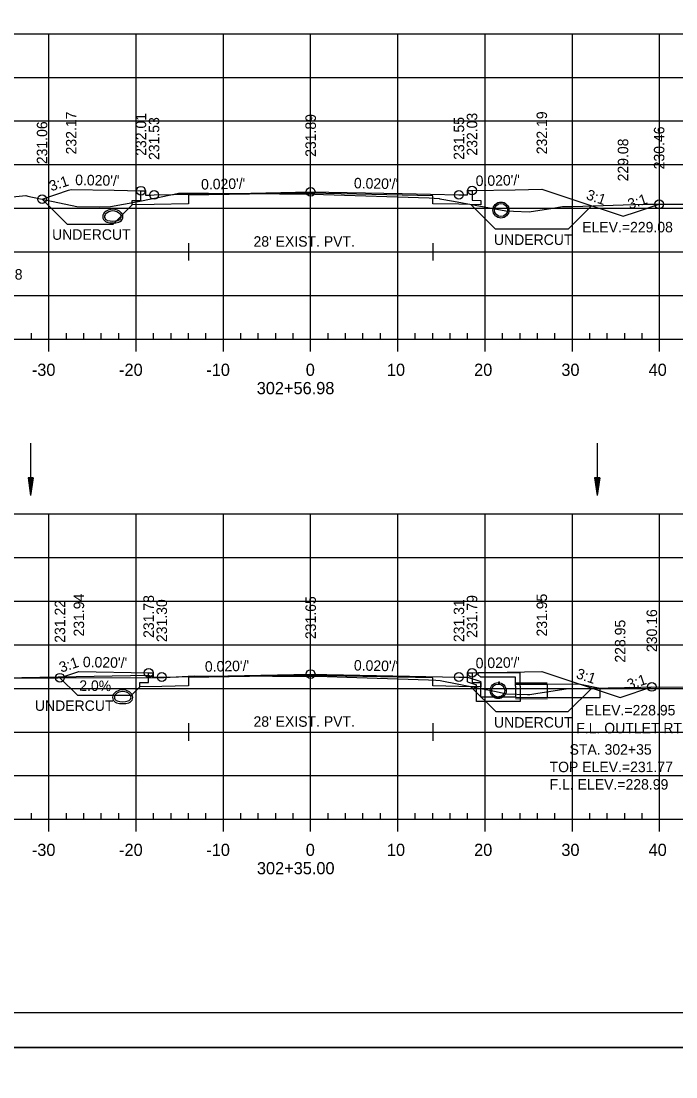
# Model space of a CAD drawing. Extents: x 1386544 to 1388153, y 379785 to 390999.
# Drawn here: x 1386681.7 to 1386756.7, y 384488.6 to 384609.5 of the extents above; entities that cross this region are included whole.
import ezdxf

# ---------------------------------------------------------------- set-up
doc = ezdxf.new("R2010")
doc.units = 0
for name, color, linetype in [('R_Alt Surface', 7, 'Continuous'), ('R_Axis', 7, 'Continuous'), ('R_Axis Annot', 7, 'Continuous'), ('R_Border', 7, 'Continuous'), ('R_Dimension', 7, 'Continuous'), ('R_Drive', 7, 'Continuous'), ('R_Exist Surface', 7, 'Continuous'), ('R_Fin Surface', 7, 'Continuous'), ('R_Fin Surface Annot', 7, 'Continuous'), ('R_Grid', 7, 'Continuous'), ('R_No Plot', 7, 'Continuous'), ('R_Water', 7, 'Continuous'), ('R_Water Annot', 7, 'Continuous')]:
    doc.layers.add(name, color=color, linetype=linetype)

msp = doc.modelspace()

# ---------------------------------------------------------------- linework, layer by layer
at = {"layer": 'R_Alt Surface'}
for points in [[(1386733.37, 384590.12), (1386733.37, 384589.02), (1386734.37, 384589), (1386734.37, 384588.5), (1386731.87, 384588.55), (1386728.87, 384588.61), (1386728.87, 384589.53), (1386714.87, 384589.81), (1386700.87, 384589.6), (1386700.87, 384588.61), (1386696.92, 384588.53), (1386694.42, 384588.48), (1386694.42, 384588.98), (1386695.42, 384589), (1386695.42, 384590.1)], [(1386700.87, 384584.09), (1386700.87, 384582.09)], [(1386728.87, 384584.09), (1386728.87, 384582.09)], [(1386700.87, 384583.09), (1386728.87, 384583.09)], [(1386733.37, 384534.87), (1386733.37, 384533.78), (1386734.37, 384533.76), (1386734.37, 384533.26), (1386731.87, 384533.31), (1386728.87, 384533.37), (1386728.87, 384534.28), (1386714.87, 384534.56), (1386700.87, 384534.35), (1386700.87, 384533.37), (1386697.8, 384533.31), (1386695.3, 384533.26), (1386695.3, 384533.76), (1386696.3, 384533.78), (1386696.3, 384534.87)], [(1386700.87, 384529.09), (1386700.87, 384527.09)], [(1386728.87, 384529.09), (1386728.87, 384527.09)], [(1386700.87, 384528.09), (1386728.87, 384528.09)]]:
    msp.add_lwpolyline(points, dxfattribs=at)
at = {"layer": 'R_Axis'}
for p, q in [((1386682.87, 384573.09), (1386682.87, 384573.79)), ((1386686.87, 384573.09), (1386686.87, 384573.79)), ((1386688.87, 384573.09), (1386688.87, 384573.79)), ((1386690.87, 384573.09), (1386690.87, 384573.79)), ((1386692.87, 384573.09), (1386692.87, 384573.79)), ((1386696.87, 384573.09), (1386696.87, 384573.79)), ((1386698.87, 384573.09), (1386698.87, 384573.79)), ((1386700.87, 384573.09), (1386700.87, 384573.79)), ((1386702.87, 384573.09), (1386702.87, 384573.79)), ((1386706.87, 384573.09), (1386706.87, 384573.79)), ((1386708.87, 384573.09), (1386708.87, 384573.79)), ((1386710.87, 384573.09), (1386710.87, 384573.79)), ((1386712.87, 384573.09), (1386712.87, 384573.79)), ((1386716.87, 384573.09), (1386716.87, 384573.79)), ((1386718.87, 384573.09), (1386718.87, 384573.79)), ((1386720.87, 384573.09), (1386720.87, 384573.79)), ((1386722.87, 384573.09), (1386722.87, 384573.79)), ((1386726.87, 384573.09), (1386726.87, 384573.79)), ((1386728.87, 384573.09), (1386728.87, 384573.79)), ((1386730.87, 384573.09), (1386730.87, 384573.79)), ((1386732.87, 384573.09), (1386732.87, 384573.79)), ((1386736.87, 384573.09), (1386736.87, 384573.79)), ((1386738.87, 384573.09), (1386738.87, 384573.79)), ((1386740.87, 384573.09), (1386740.87, 384573.79)), ((1386742.87, 384573.09), (1386742.87, 384573.79)), ((1386746.87, 384573.09), (1386746.87, 384573.79)), ((1386748.87, 384573.09), (1386748.87, 384573.79)), ((1386750.87, 384573.09), (1386750.87, 384573.79)), ((1386752.87, 384573.09), (1386752.87, 384573.79)), ((1386569.87, 384573.09), (1386859.87, 384573.09)), ((1386684.87, 384571.69), (1386684.87, 384573.09)), ((1386694.87, 384571.69), (1386694.87, 384573.09)), ((1386704.87, 384571.69), (1386704.87, 384573.09)), ((1386714.87, 384571.69), (1386714.87, 384573.09)), ((1386724.87, 384571.69), (1386724.87, 384573.09)), ((1386734.87, 384571.69), (1386734.87, 384573.09)), ((1386744.87, 384571.69), (1386744.87, 384573.09)), ((1386754.87, 384571.69), (1386754.87, 384573.09)), ((1386569.87, 384518.09), (1386859.87, 384518.09)), ((1386682.87, 384518.09), (1386682.87, 384518.79)), ((1386684.87, 384516.69), (1386684.87, 384518.09)), ((1386686.87, 384518.09), (1386686.87, 384518.79)), ((1386688.87, 384518.09), (1386688.87, 384518.79)), ((1386690.87, 384518.09), (1386690.87, 384518.79)), ((1386692.87, 384518.09), (1386692.87, 384518.79)), ((1386694.87, 384516.69), (1386694.87, 384518.09)), ((1386696.87, 384518.09), (1386696.87, 384518.79)), ((1386698.87, 384518.09), (1386698.87, 384518.79)), ((1386700.87, 384518.09), (1386700.87, 384518.79)), ((1386702.87, 384518.09), (1386702.87, 384518.79)), ((1386704.87, 384516.69), (1386704.87, 384518.09)), ((1386706.87, 384518.09), (1386706.87, 384518.79)), ((1386708.87, 384518.09), (1386708.87, 384518.79)), ((1386710.87, 384518.09), (1386710.87, 384518.79)), ((1386712.87, 384518.09), (1386712.87, 384518.79)), ((1386714.87, 384516.69), (1386714.87, 384518.09)), ((1386716.87, 384518.09), (1386716.87, 384518.79)), ((1386718.87, 384518.09), (1386718.87, 384518.79)), ((1386720.87, 384518.09), (1386720.87, 384518.79)), ((1386722.87, 384518.09), (1386722.87, 384518.79)), ((1386724.87, 384516.69), (1386724.87, 384518.09)), ((1386726.87, 384518.09), (1386726.87, 384518.79)), ((1386728.87, 384518.09), (1386728.87, 384518.79)), ((1386730.87, 384518.09), (1386730.87, 384518.79)), ((1386732.87, 384518.09), (1386732.87, 384518.79)), ((1386734.87, 384516.69), (1386734.87, 384518.09)), ((1386736.87, 384518.09), (1386736.87, 384518.79)), ((1386738.87, 384518.09), (1386738.87, 384518.79)), ((1386740.87, 384518.09), (1386740.87, 384518.79)), ((1386742.87, 384518.09), (1386742.87, 384518.79)), ((1386744.87, 384516.69), (1386744.87, 384518.09)), ((1386746.87, 384518.09), (1386746.87, 384518.79)), ((1386748.87, 384518.09), (1386748.87, 384518.79)), ((1386750.87, 384518.09), (1386750.87, 384518.79)), ((1386752.87, 384518.09), (1386752.87, 384518.79)), ((1386754.87, 384516.69), (1386754.87, 384518.09))]:
    msp.add_line(p, q, dxfattribs=at)
at = {"layer": 'R_Border'}
msp.add_line((1386873.05, 384495.92), (1386556.87, 384495.92), dxfattribs=at)
at = {"layer": 'R_Dimension'}
for p, q in [((1386684.08, 384589.14), (1386686.94, 384586.28)), ((1386694.42, 384588.48), (1386692.22, 384586.28)), ((1386733.23, 384588.53), (1386736.06, 384585.69)), ((1386747.08, 384588.37), (1386744.4, 384585.69)), ((1386686.13, 384534.31), (1386688.13, 384532.31)), ((1386695.3, 384533.26), (1386694.35, 384532.31)), ((1386733.25, 384533.28), (1386736.15, 384530.39)), ((1386747.09, 384533.13), (1386744.34, 384530.39))]:
    msp.add_line(p, q, dxfattribs=at)
for points in [[(1386686.94, 384586.28), (1386692.22, 384586.28)], [(1386744.4, 384585.69), (1386736.06, 384585.69)], [(1386688.13, 384532.31), (1386694.35, 384532.31)], [(1386744.34, 384530.39), (1386736.15, 384530.39)]]:
    msp.add_lwpolyline(points, dxfattribs=at)
at = {"layer": 'R_Drive'}
for p, q in [((1386696.3, 384534.57), (1386681.77, 384534.28)), ((1386696.8, 384534.37), (1386696.3, 384534.57))]:
    msp.add_line(p, q, dxfattribs=at)
at = {"layer": 'R_Exist Surface'}
for points in [[(1386677.97, 384589.12), (1386682.21, 384589.54), (1386682.45, 384589.49), (1386688.07, 384588.28), (1386690.72, 384588.27), (1386691.91, 384588.31), (1386694.9, 384588.81), (1386699.21, 384589.72), (1386699.72, 384589.82), (1386701.38, 384589.83), (1386701.39, 384589.83), (1386703.17, 384589.81), (1386715.34, 384589.69), (1386716.35, 384589.66), (1386728.44, 384589.3), (1386729.59, 384589.2), (1386729.69, 384589.19), (1386731.26, 384588.89), (1386737.26, 384587.78), (1386738.11, 384587.75), (1386739.93, 384587.69), (1386742.63, 384588.11), (1386743.76, 384588.29), (1386744.94, 384588.31), (1386753.01, 384588.55), (1386764.32, 384588.55)], [(1386680.87, 384534.28), (1386682.6, 384534.28), (1386685.88, 384534.31), (1386698.08, 384534.33), (1386701.52, 384534.54), (1386710.48, 384534.48), (1386715.61, 384534.47), (1386720.16, 384534.32), (1386728.38, 384534.07), (1386729.22, 384534.01), (1386729.72, 384533.98), (1386736.13, 384532.72), (1386737.31, 384532.47), (1386739.73, 384532.39), (1386739.99, 384532.39), (1386740.7, 384532.49), (1386744.4, 384533.09), (1386747.09, 384533.13), (1386752.72, 384533.24), (1386769.44, 384533.32)]]:
    msp.add_lwpolyline(points, dxfattribs=at)
at = {"layer": 'R_Fin Surface'}
for points in [[(1386684.08, 384589.14), (1386687.11, 384590.16), (1386687.42, 384590.26), (1386692.35, 384590.16), (1386695.42, 384590.1), (1386695.73, 384590.1), (1386695.92, 384590.1), (1386695.92, 384589.79), (1386695.92, 384589.6), (1386696.54, 384589.61), (1386696.92, 384589.62), (1386708.02, 384589.84), (1386714.87, 384589.98), (1386725.36, 384589.77), (1386731.87, 384589.64), (1386732.25, 384589.63), (1386732.87, 384589.62), (1386732.87, 384589.93), (1386732.87, 384590.12), (1386733.06, 384590.12), (1386733.37, 384590.12), (1386738.3, 384590.22), (1386741.37, 384590.28), (1386744.93, 384589.09), (1386750.68, 384587.17), (1386752.24, 384587.69), (1386754.82, 384588.55)], [(1386686.13, 384534.31), (1386688.3, 384535.03), (1386696.3, 384534.87), (1386696.8, 384534.87), (1386696.8, 384534.37), (1386697.8, 384534.39), (1386714.87, 384534.73), (1386731.87, 384534.39), (1386732.87, 384534.37), (1386732.87, 384534.87), (1386733.37, 384534.87), (1386741.37, 384535.03), (1386750.35, 384532.04), (1386753.98, 384533.25)]]:
    msp.add_lwpolyline(points, dxfattribs=at)
at = {"layer": 'R_Grid'}
for p, q in [((1386569.87, 384608.09), (1386859.87, 384608.09)), ((1386684.87, 384573.09), (1386684.87, 384608.09)), ((1386694.87, 384573.09), (1386694.87, 384608.09)), ((1386704.87, 384573.09), (1386704.87, 384608.09)), ((1386714.87, 384573.09), (1386714.87, 384608.09)), ((1386724.87, 384573.09), (1386724.87, 384608.09)), ((1386734.87, 384573.09), (1386734.87, 384608.09)), ((1386744.87, 384573.09), (1386744.87, 384608.09)), ((1386754.87, 384573.09), (1386754.87, 384608.09)), ((1386569.87, 384603.09), (1386859.87, 384603.09)), ((1386569.87, 384598.09), (1386859.87, 384598.09)), ((1386569.87, 384593.09), (1386859.87, 384593.09)), ((1386569.87, 384588.09), (1386859.87, 384588.09)), ((1386569.87, 384583.09), (1386859.87, 384583.09)), ((1386569.87, 384578.09), (1386859.87, 384578.09)), ((1386569.87, 384573.09), (1386859.87, 384573.09)), ((1386569.87, 384553.09), (1386859.87, 384553.09)), ((1386684.87, 384518.09), (1386684.87, 384553.09)), ((1386694.87, 384518.09), (1386694.87, 384553.09)), ((1386704.87, 384518.09), (1386704.87, 384553.09)), ((1386714.87, 384518.09), (1386714.87, 384553.09)), ((1386724.87, 384518.09), (1386724.87, 384553.09)), ((1386734.87, 384518.09), (1386734.87, 384553.09)), ((1386744.87, 384518.09), (1386744.87, 384553.09)), ((1386754.87, 384518.09), (1386754.87, 384553.09)), ((1386569.87, 384548.09), (1386859.87, 384548.09)), ((1386569.87, 384543.09), (1386859.87, 384543.09)), ((1386569.87, 384538.09), (1386859.87, 384538.09)), ((1386569.87, 384533.09), (1386859.87, 384533.09)), ((1386569.87, 384528.09), (1386859.87, 384528.09)), ((1386569.87, 384523.09), (1386859.87, 384523.09)), ((1386569.87, 384518.09), (1386859.87, 384518.09))]:
    msp.add_line(p, q, dxfattribs=at)
at = {"layer": 'R_No Plot'}
for p, q in [((1386736.51, 384533.83), (1386736.4, 384533.75)), ((1386738.37, 384533.74), (1386741.98, 384533.73)), ((1386736.51, 384532), (1386736.4, 384531.91)), ((1386738.37, 384531.91), (1386741.98, 384531.9)), ((1386544.47, 384491.94), (1386877.8, 384491.94)), ((1386544.47, 384491.94), (1386877.8, 384491.94))]:
    msp.add_line(p, q, dxfattribs=at)
for points in [[(1386544.46, 384705.28), (1386877.8, 384705.28), (1386877.8, 384491.94), (1386544.46, 384491.94)], [(1386790.79, 384701.38), (1386810.41, 384701.38), (1386810.41, 384691.5), (1386826.52, 384691.5), (1386849.72, 384691.5), (1386849.72, 384667.17), (1386873.05, 384667.17), (1386873.05, 384495.92), (1386556.87, 384495.92), (1386556.87, 384701.38)], [(1386544.46, 384491.94), (1386877.8, 384491.94), (1386877.8, 384278.6), (1386544.46, 384278.6)]]:
    msp.add_lwpolyline(points, close=True, dxfattribs=at)
for centre, radius in [((1386695.42, 384590.1), 0.5), ((1386714.87, 384589.98), 0.5), ((1386733.37, 384590.12), 0.5), ((1386684.08, 384589.14), 0.5), ((1386696.92, 384589.62), 0.5), ((1386731.87, 384589.64), 0.5), ((1386736.69, 384587.89), 0.917), ((1386754.82, 384588.55), 0.5), ((1386686.13, 384534.31), 0.5), ((1386696.3, 384534.87), 0.5), ((1386697.8, 384534.39), 0.5), ((1386714.87, 384534.73), 0.5), ((1386731.87, 384534.39), 0.5), ((1386733.37, 384534.87), 0.5), ((1386736.37, 384532.83), 0.917), ((1386753.98, 384533.25), 0.5)]:
    msp.add_circle(centre, radius, dxfattribs=at)
for centre, radius, start, end in [((1386692.19, 384586.64), 1.35, 43.6485, 136.3515), ((1386691.68, 384587.13), 0.646, 136.3515, 253.9529), ((1386692.71, 384587.13), 0.646, 286.0471, 43.6485), ((1386692.19, 384588.91), 2.5, 253.9529, 286.0471), ((1386692.81, 384532.07), 0.646, 136.3515, 253.9529), ((1386693.32, 384531.58), 1.35, 43.6485, 136.3515), ((1386693.84, 384532.07), 0.646, 286.0471, 43.6485), ((1386693.32, 384533.85), 2.5, 253.9529, 286.0471)]:
    msp.add_arc(centre, radius, start, end, dxfattribs=at)
at = {"layer": 'R_Water'}
for p, q in [((1386682.77, 384561.19), (1386682.77, 384555.19)), ((1386747.71, 384561.19), (1386747.71, 384555.19)), ((1386682.47, 384557.19), (1386682.77, 384555.19)), ((1386683.07, 384557.19), (1386682.47, 384557.19)), ((1386682.47, 384557.19), (1386682.77, 384555.19)), ((1386683.07, 384557.19), (1386682.47, 384557.19)), ((1386682.52, 384557.19), (1386682.77, 384555.52)), ((1386682.52, 384557.19), (1386682.77, 384555.52)), ((1386682.57, 384557.19), (1386682.77, 384555.87)), ((1386682.57, 384557.19), (1386682.77, 384555.87)), ((1386682.62, 384557.19), (1386682.77, 384556.2)), ((1386682.62, 384557.19), (1386682.77, 384556.2)), ((1386682.68, 384557.19), (1386682.77, 384556.54)), ((1386682.68, 384557.19), (1386682.77, 384556.54)), ((1386682.73, 384557.19), (1386682.77, 384556.87)), ((1386682.73, 384557.19), (1386682.77, 384556.87)), ((1386683.07, 384557.19), (1386682.77, 384555.19)), ((1386682.87, 384557.19), (1386682.77, 384556.54)), ((1386682.97, 384557.19), (1386682.77, 384555.87)), ((1386683.02, 384557.19), (1386682.77, 384555.52)), ((1386682.92, 384557.19), (1386682.77, 384556.2)), ((1386682.82, 384557.19), (1386682.77, 384556.87)), ((1386683.07, 384557.19), (1386682.77, 384555.19)), ((1386682.87, 384557.19), (1386682.77, 384556.54)), ((1386682.97, 384557.19), (1386682.77, 384555.87)), ((1386683.02, 384557.19), (1386682.77, 384555.52)), ((1386682.92, 384557.19), (1386682.77, 384556.2)), ((1386682.82, 384557.19), (1386682.77, 384556.87)), ((1386747.41, 384557.19), (1386747.71, 384555.19)), ((1386748.01, 384557.19), (1386747.41, 384557.19)), ((1386747.41, 384557.19), (1386747.71, 384555.19)), ((1386748.01, 384557.19), (1386747.41, 384557.19)), ((1386747.46, 384557.19), (1386747.71, 384555.52)), ((1386747.46, 384557.19), (1386747.71, 384555.52)), ((1386747.51, 384557.19), (1386747.71, 384555.87)), ((1386747.51, 384557.19), (1386747.71, 384555.87)), ((1386747.56, 384557.19), (1386747.71, 384556.2)), ((1386747.56, 384557.19), (1386747.71, 384556.2)), ((1386747.61, 384557.19), (1386747.71, 384556.54)), ((1386747.61, 384557.19), (1386747.71, 384556.54)), ((1386747.66, 384557.19), (1386747.71, 384556.87)), ((1386747.66, 384557.19), (1386747.71, 384556.87)), ((1386748.01, 384557.19), (1386747.71, 384555.19)), ((1386747.81, 384557.19), (1386747.71, 384556.54)), ((1386747.91, 384557.19), (1386747.71, 384555.87)), ((1386747.96, 384557.19), (1386747.71, 384555.52)), ((1386747.86, 384557.19), (1386747.71, 384556.2)), ((1386747.76, 384557.19), (1386747.71, 384556.87)), ((1386748.01, 384557.19), (1386747.71, 384555.19)), ((1386747.81, 384557.19), (1386747.71, 384556.54)), ((1386747.91, 384557.19), (1386747.71, 384555.87)), ((1386747.96, 384557.19), (1386747.71, 384555.52)), ((1386747.86, 384557.19), (1386747.71, 384556.2)), ((1386747.76, 384557.19), (1386747.71, 384556.87)), ((1386734.04, 384534.69), (1386734.12, 384534.86)), ((1386738.87, 384534.86), (1386734.12, 384534.86)), ((1386738.87, 384533.36), (1386738.87, 384534.86)), ((1386732.87, 384534.38), (1386734.37, 384533.86)), ((1386732.87, 384533.85), (1386733.87, 384533.5)), ((1386734.04, 384534.69), (1386734.37, 384534.36)), ((1386738.37, 384534.36), (1386734.37, 384534.36)), ((1386734.37, 384533.36), (1386734.37, 384533.86)), ((1386736.51, 384533.66), (1386736.4, 384533.58)), ((1386738.37, 384533.36), (1386738.37, 384534.36)), ((1386738.37, 384533.57), (1386741.98, 384533.56)), ((1386733.87, 384533.36), (1386733.87, 384533.5)), ((1386736.51, 384532.16), (1386736.4, 384532.08)), ((1386738.37, 384532.07), (1386741.98, 384532.06))]:
    msp.add_line(p, q, dxfattribs=at)
for points in [[(1386732.87, 384533.85), (1386732.87, 384534.38)], [(1386738.87, 384533.36), (1386738.87, 384531.57), (1386736.37, 384531.57), (1386733.87, 384531.57), (1386733.87, 384533.36)], [(1386738.37, 384533.36), (1386738.37, 384532.07), (1386736.37, 384532.07), (1386734.37, 384532.07), (1386734.37, 384533.36)]]:
    msp.add_lwpolyline(points, dxfattribs=at)
msp.add_lwpolyline([(1386741.98, 384533.56), (1386741.98, 384532.06), (1386748.06, 384532.05), (1386748.07, 384533.09), (1386745.82, 384533.55)], close=True, dxfattribs=at)
for centre in [(1386736.69, 384587.89), (1386736.37, 384532.83)]:
    msp.add_circle(centre, 0.75, dxfattribs=at)
for centre, radius, start, end in [((1386691.68, 384587.13), 0.438, 136.3515, 253.9529), ((1386692.19, 384586.64), 1.15, 43.6485, 136.3515), ((1386692.71, 384587.13), 0.438, 286.0471, 43.6485), ((1386692.19, 384588.91), 2.29, 253.9529, 286.0471), ((1386692.81, 384532.07), 0.438, 136.3515, 253.9529), ((1386693.32, 384531.58), 1.15, 43.6485, 136.3515), ((1386693.84, 384532.07), 0.438, 286.0471, 43.6485), ((1386693.32, 384533.85), 2.29, 253.9529, 286.0471)]:
    msp.add_arc(centre, radius, start, end, dxfattribs=at)

# ---------------------------------------------------------------- texts
at = {"layer": 'R_Axis Annot'}
for s, p in [('-30', (1386682.91, 384568.89)), ('-20', (1386692.91, 384568.89)), ('-10', (1386702.91, 384568.89)), ('0', (1386714.31, 384568.89)), ('10', (1386723.61, 384568.89)), ('20', (1386733.61, 384568.89)), ('30', (1386743.61, 384568.89)), ('40', (1386753.61, 384568.89)), ('302+56.98', (1386708.69, 384566.79)), ('-30', (1386682.91, 384513.89)), ('-20', (1386692.91, 384513.89)), ('-10', (1386702.91, 384513.89)), ('0', (1386714.31, 384513.89)), ('10', (1386723.61, 384513.89)), ('20', (1386733.61, 384513.89)), ('30', (1386743.61, 384513.89)), ('40', (1386753.61, 384513.89)), ('302+35.00', (1386708.71, 384511.79))]:
    msp.add_text(s, height=1.4, dxfattribs=at).set_placement(p)
at = {"layer": 'R_Dimension'}
for p in [(1386685.23, 384584.48), (1386735.88, 384583.89), (1386683.26, 384530.51), (1386735.89, 384528.59)]:
    msp.add_text('UNDERCUT', height=1.2, dxfattribs=at).set_placement(p)
at = {"layer": 'R_Drive'}
msp.add_text('2.0%', height=1.2, rotation=359.427, dxfattribs=at).set_placement((1386688.34, 384532.81))
at = {"layer": 'R_Fin Surface Annot'}
for s, rotation, p in [('232.17', 90, (1386688.02, 384594.26)), ('232.01', 90, (1386696.02, 384594.1)), ('232.03', 90, (1386733.97, 384594.12)), ('232.19', 90, (1386741.97, 384594.28)), ('231.06', 90, (1386684.68, 384593.14)), ('231.53', 90, (1386697.52, 384593.62)), ('231.89', 90, (1386715.47, 384593.98)), ('231.55', 90, (1386732.47, 384593.64)), ('230.46', 90, (1386755.42, 384592.55)), ('229.08', 90, (1386751.28, 384591.17)), ('3:1', 18.4349, (1386685.13, 384590.02)), ("0.020'/'", 358.8542, (1386687.87, 384590.75)), ("0.020'/'", 1.1458, (1386733.8, 384590.63)), ("0.020'/'", 1.1458, (1386702.32, 384590.23)), ("0.020'/'", 358.8542, (1386719.82, 384590.38)), ('3:1', 341.5651, (1386746.37, 384589.15)), ('3:1', 18.4349, (1386751.45, 384587.95)), ('231.94', 90, (1386688.9, 384539.03)), ('231.78', 90, (1386696.9, 384538.87)), ('231.65', 90, (1386715.47, 384538.73)), ('231.79', 90, (1386733.97, 384538.87)), ('231.95', 90, (1386741.97, 384539.03)), ('231.22', 90, (1386686.73, 384538.31)), ('231.30', 90, (1386698.4, 384538.39)), ('231.31', 90, (1386732.47, 384538.39)), ('230.16', 90, (1386754.58, 384537.25)), ('228.95', 90, (1386750.95, 384536.04)), ('3:1', 18.4349, (1386686.27, 384534.88)), ("0.020'/'", 358.8542, (1386688.75, 384535.52)), ("0.020'/'", 1.1458, (1386702.76, 384534.99)), ("0.020'/'", 358.8542, (1386719.82, 384535.14)), ("0.020'/'", 1.1458, (1386733.8, 384535.38)), ('3:1', 341.5651, (1386745.21, 384534.29)), ('3:1', 18.4349, (1386751.37, 384532.91))]:
    msp.add_text(s, height=1.2, rotation=rotation, dxfattribs=at).set_placement(p)
for s, p in [('ELEV.=229.08', (1386746, 384585.33)), ('ELEV.=228.95', (1386746.29, 384529.99))]:
    msp.add_text(s, height=1.2, dxfattribs=at).set_placement(p)
at = {"layer": 'R_No Plot'}
for p in [(1386687.38, 384590.21), (1386741.33, 384590.23), (1386688.26, 384534.98), (1386741.33, 384534.98)]:
    msp.add_text('+', height=0.1, dxfattribs=at).set_placement(p)
at = {"layer": 'R_Water'}
for p in [(1386708.32, 384583.69), (1386708.32, 384528.69)]:
    msp.add_text("28' EXIST. PVT.", height=1.2, dxfattribs=at).set_placement(p)
at = {"layer": 'R_Water Annot'}
for s, p in [('TOP ELEV.=230.78', (1386667.7, 384579.92)), ('F.L. OUTLET RT. = 228.95', (1386745.32, 384527.94)), ('STA. 302+35', (1386744.55, 384525.49)), ('TOP ELEV.=231.77', (1386742.26, 384523.49)), ('F.L. ELEV.=228.99', (1386742.27, 384521.49))]:
    msp.add_text(s, height=1.2, dxfattribs=at).set_placement(p)

doc.saveas('drawing.dxf')
